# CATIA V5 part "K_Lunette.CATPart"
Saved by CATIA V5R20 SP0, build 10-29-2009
Part number: Lunette
Publications: "diametrelunette"
Bounding box of the stored display mesh (mm): x -18.659 to 18.659, y -59.459 to 120, z 31.341 to 68.659
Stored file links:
  G:\Khaled_CFAO_2011\SIL\SIL_GR2\mdupuis\Khaled\CAD_ThinkMOTION\K_Lunette.CATPart
  G:\Dupuis_Maxime_Thinkmotion_CFAO\assemblage.CATProduct
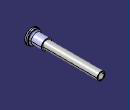
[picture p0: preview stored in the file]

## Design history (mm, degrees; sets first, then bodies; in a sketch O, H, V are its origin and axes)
Parameters
  diametrelunette = 20 mm
Set1
  Plane1: linked copy from another document
  Point1: linked copy from another document
  Plane2: linked copy from another document
  Line1: linked copy from another document
Body1 (main body)
  Sketch1 on Plane1, origin (0, 0, 0), H (-1, 0, 0), V (0, 0, 1)
    circle A1 centre (0, 50) radius 10
    point P1 (0, 50)
    reference projected point E1 (0, 50) from Point1
    radius A1 = 10 {= diametrelunette/2}
    coincidence: P1 E1
  Pad1: profile Sketch1, direction (0, 1, 0), length 120, opposite side length 20
  Sketch2 on Plane1, origin (0, 0, 0), H (-1, 0, 0), V (0, 0, 1)
    circle A1 centre (0, 50) radius 13
    point P1 (0, 50)
    reference projected point E1 (0, 50) from Point1
    radius A1 = 13 {= (diametrelunette /2)+3mm}
    coincidence: P1 V, P1 E1
  Pad2: profile Sketch2, direction (0, 1, 0), length -50, opposite side length 20
  Sketch3 on yz-plane, origin (0, 0, 0), H (0, 1, 0), V (0, 0, 1)
    point P1 (-57.464, 68.6643)
    line L1 (-57.464, 68.6643) -> (-54.2609, 68.6643)
    line L2 (-54.2609, 68.6643) -> (-51.395, 67.0632)
    line L3 (-51.395, 67.0632) -> (-50, 66.6952)
    line L4 (-50, 66.6952) -> (-50, 50)
    arc A1 centre (-50, 66.6952) radius 0 from (-50, 66.6952) to (-50, 66.6952) cw
    reference projected line E1 (-50, 63) -> (-50, 37) from edge [end face of Pad2 | face of Pad2 from Sketch2.A1]
    axis line L5 (-62, 50) -> (-42, 50)
    line L6 (-57.464, 68.6643) -> (-57.464, 50)
    point P10 (-57.464, 50)
    radius A1 = 0
    horizontal: L1 H, L5 H
    coincidence: L3 P1, L4 E1, P10 L5
    vertical: L4 V, L6 V
    tangency: A1 L3, A1 L4
  Shaft1: profile Sketch3, axis Sketch3.L5, angle 360
  FaceFillet1: Radius 3.65, Face1 face of Shaft1 from Sketch3.L4, Face2 face of Pad2 from Sketch2.A1, ConicRatio 0.5
  Sketch4 on face of Shaft1 from Sketch3.L6, origin (0, -57.464, 0), H (1, 0, 0), V (0, 0, 1)
    circle A1 centre (0, 50) radius 14.3178
    point P1 (0, 50)
    coincidence: P1 V
  Pocket1: profile Sketch4, direction (0, -1, 0), length -2
  Point2: type OnSurface, Support end face of Pocket1, Length 0, Direction (0.7821, -0.1156, 0.6123)
  Point3: (0, 25, 0), relative to Point2
  DatumSurface1
  Sketch5 on end face of Pad1, origin (0, 120, 0), H (-1, 0, 0), V (0, 0, 1)
    circle A1 centre (0, 50) radius 8.0623
    point P1 (0, 50)
    coincidence: P1 V
  Pocket2: profile Sketch5, direction (0, 1, 0), up to end face of Pocket1
  Fill1: Boundary edge [end face of Pad1 | face of Pocket2 from Sketch5.A1]
Body2
  DatumSurface2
